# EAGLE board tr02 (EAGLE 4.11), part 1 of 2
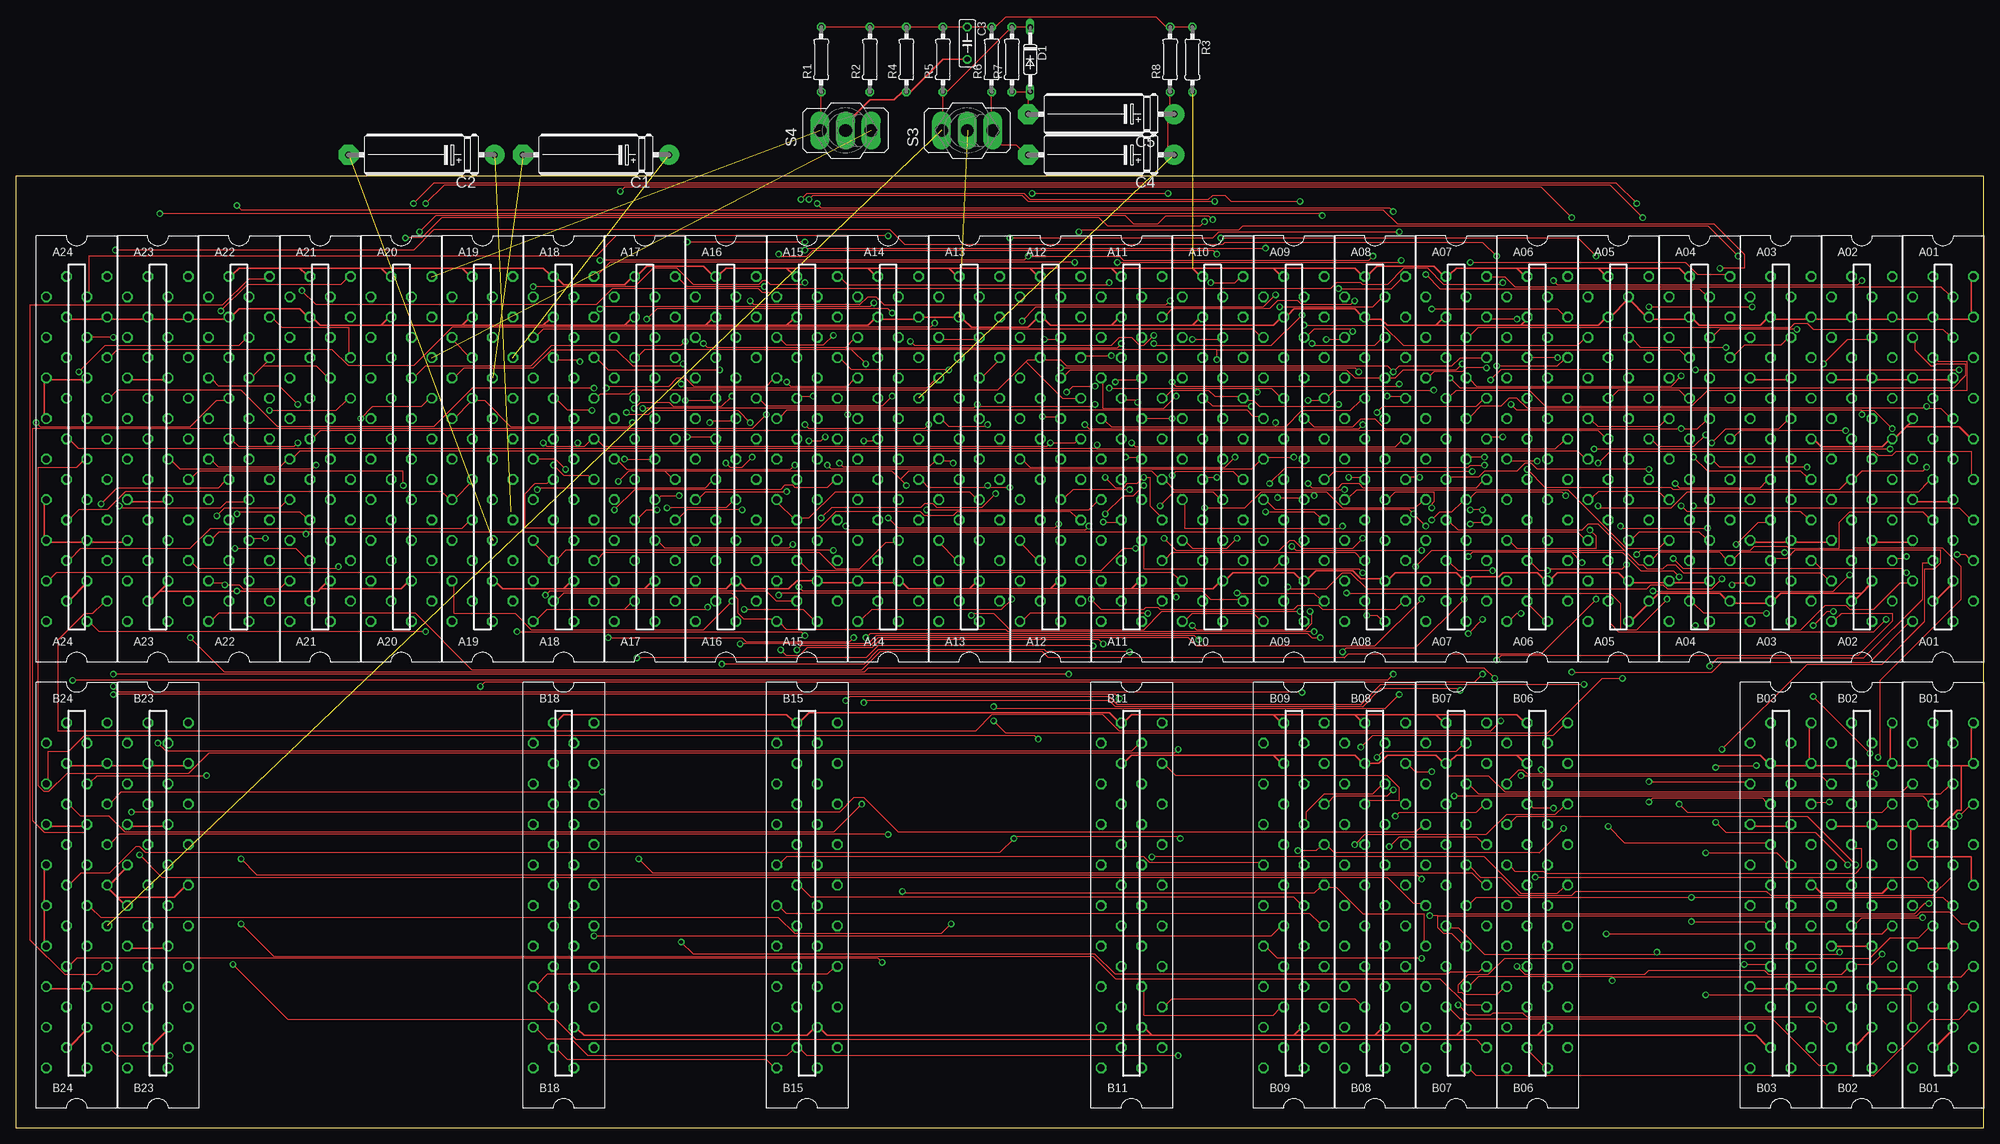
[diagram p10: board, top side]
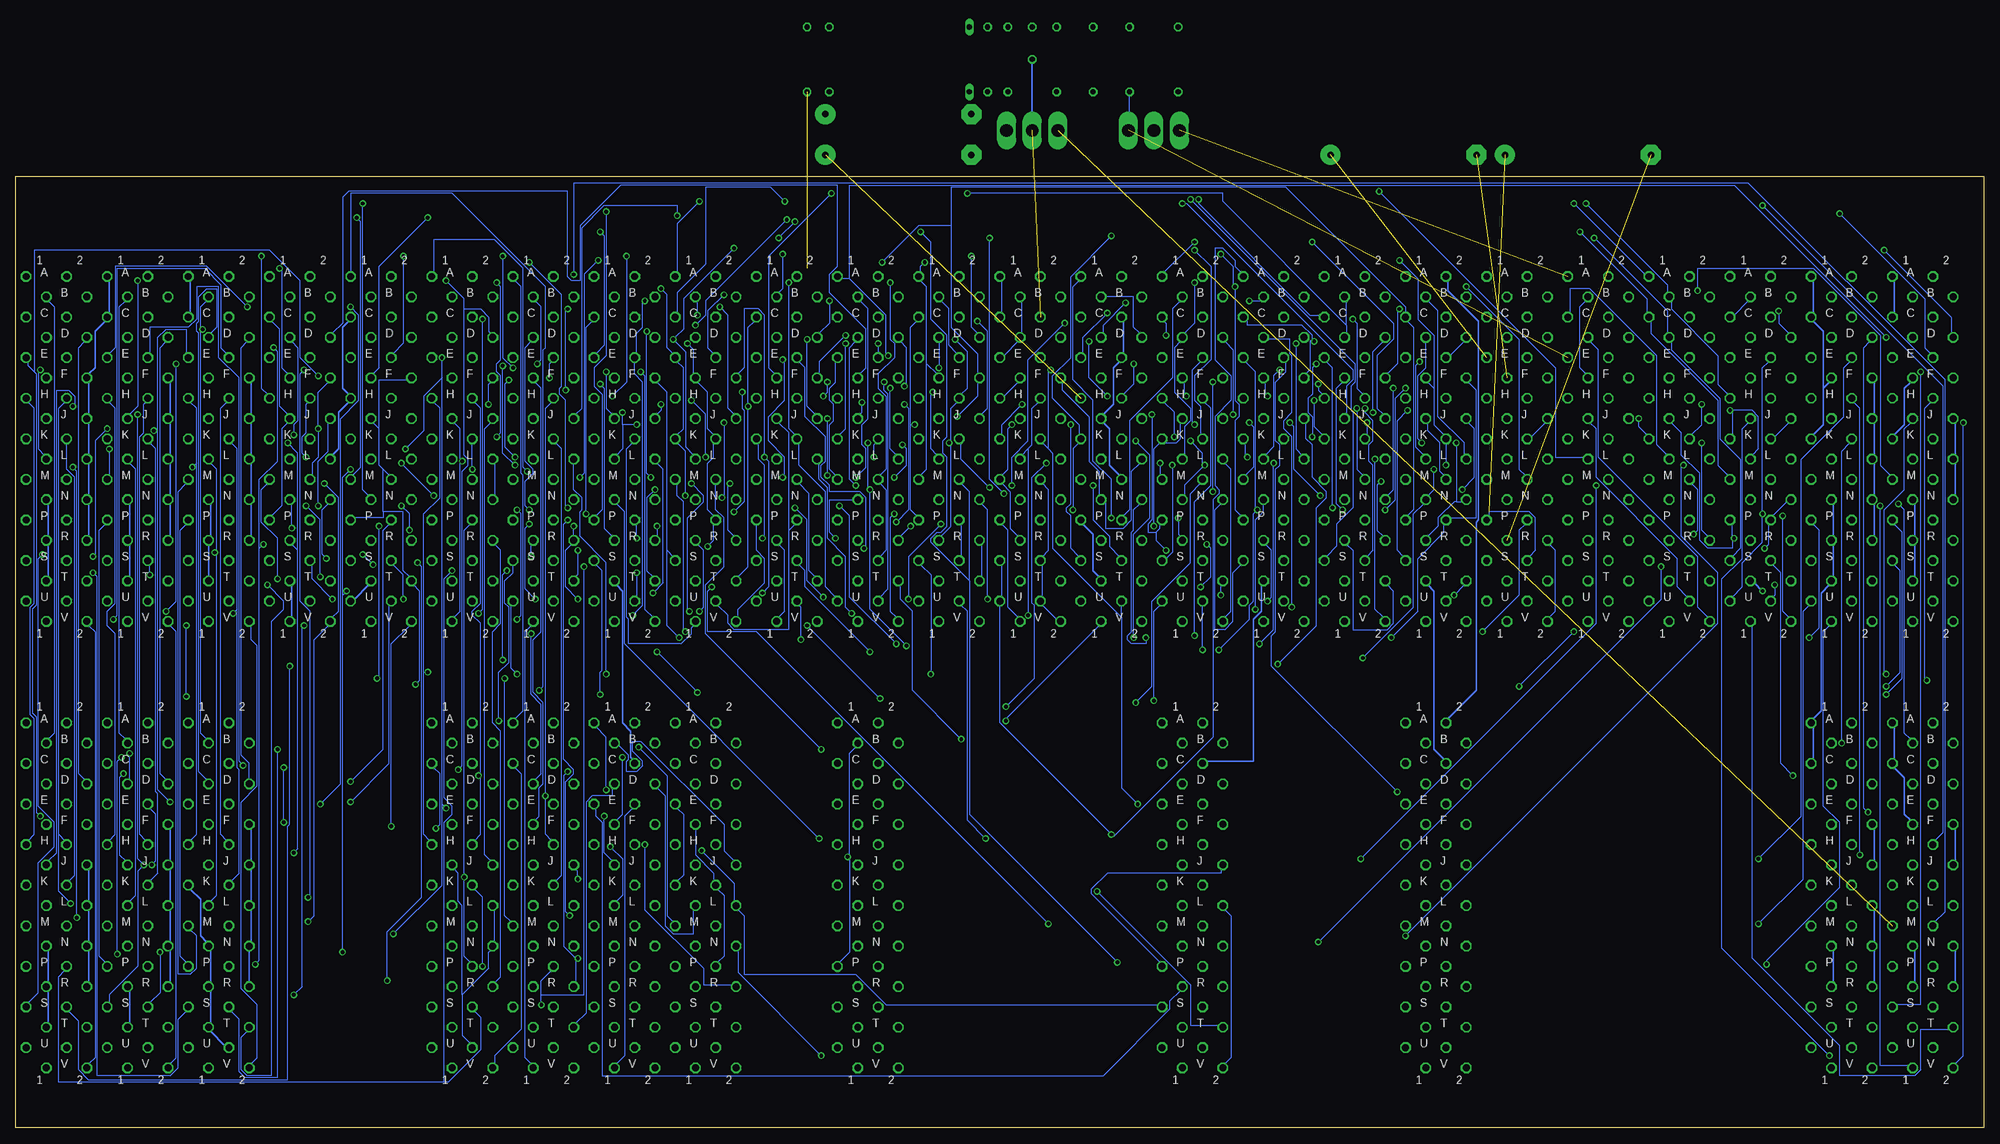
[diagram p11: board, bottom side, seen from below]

Size 307.96 x 148.9 mm. Coordinates in mm from the lower left corner, seen from the top.
Outline: 307.96,148.9 0,148.9 0,0 307.96,0 307.96,148.9
Copper layers (1*16): Top 0.035mm / dielectric 1.5mm / Bottom 0.035mm
Design rules "8mils": minimum track width 5mil, minimum drill 24mil, track to track 5mil, track to pad 8mil, pad to pad 8mil, via to via 5mil, smd to smd 8mil, copper to edge 40mil, drill to drill 10mil, minimum pad ring 10mil, minimum via ring 8mil, stop-mask expansion 0mil, vias tented up to drill 0mil, thermal gap 10mil
Net classes: 1 supply: width 0.203 mm

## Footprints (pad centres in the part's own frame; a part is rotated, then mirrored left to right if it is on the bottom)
H807 = drill 1.092 octagon: A1 4.763,28.575; A2 -1.587,28.575; B1 1.587,25.4; B2 -4.763,25.4; C1 4.763,22.225; C2 -1.587,22.225; D1 1.587,19.05; D2 -4.763,19.05; E1 4.763,15.875; E2 -1.587,15.875; F1 1.587,12.7; F2 -4.763,12.7; H1 4.763,9.525; H2 -1.587,9.525; J1 1.587,6.35; J2 -4.763,6.35; K1 4.763,3.175; K2 -1.587,3.175; L1 1.587,0; L2 -4.763,0; M1 4.763,-3.175; M2 -1.587,-3.175; N1 1.587,-6.35; N2 -4.763,-6.35; P1 4.763,-9.525; P2 -1.587,-9.525; R1 1.587,-12.7; R2 -4.763,-12.7; S1 4.763,-15.875; S2 -1.587,-15.875; T1 1.587,-19.05; T2 -4.763,-19.05; U1 4.763,-22.225; U2 -1.587,-22.225; V1 1.587,-25.4; V2 -4.763,-25.4
E22-6 = drill 1.016 pad 3.15 round: + -11.43,0 | drill 1.016 pad 3.15 octagon: - 11.43,0
C050-025X075 = drill 0.813 octagon: 1 -2.54,0; 2 2.54,0
DO35-10 = drill 0.813 long: A 5.08,0; C -5.08,0
0207/10 = drill 0.813 octagon: 1 -5.08,0; 2 5.08,0
320-916 = drill 2.007 long: 1 0,4.013; 2 0,0; 3 0,-4.013

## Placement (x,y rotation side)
A01  M903  [H807]  301.61,104.61 0 top
A02  M903  [H807]  288.91,104.61 0 top
A03  M903  [H807]  276.21,104.61 0 top
A04  [H807]  263.51,104.61 0 top
A05  [H807]  250.81,104.61 0 top
A06  [H807]  238.11,104.61 0 top
A07  M101  [H807]  225.41,104.61 0 top
A08  M111  [H807]  212.71,104.61 0 top
A09  M115  [H807]  200.01,104.61 0 top
A10  M206X  [H807]  187.31,104.61 0 top
A11  [H807]  174.61,104.61 0 top
A12  [H807]  161.91,104.61 0 top
A13  M307  [H807]  149.21,104.61 0 top
A14  M206X  [H807]  136.51,104.61 0 top
A15  M115  [H807]  123.81,104.61 0 top
A16  M111  [H807]  111.11,104.61 0 top
A17  M113  [H807]  98.41,104.61 0 top
A18  M117  [H807]  85.71,104.61 0 top
A19  [H807]  73.01,104.61 0 top
A20  M162  [H807]  60.31,104.61 0 top
A21  M162  [H807]  47.61,104.61 0 top
A22  [H807]  34.91,104.61 0 top
A23  G784  [H807]  22.21,104.61 0 top
A24  G784  [H807]  9.51,104.61 0 top
B01  M903  [H807]  301.61,34.76 0 top
B02  M903  [H807]  288.91,34.76 0 top
B03  M903  [H807]  276.21,34.76 0 top
B06  [H807]  238.11,34.76 0 top
B07  M101  [H807]  225.41,34.76 0 top
B08  M111  [H807]  212.71,34.76 0 top
B09  M115  [H807]  200.01,34.76 0 top
B11  [H807]  174.61,34.76 0 top
B15  M115  [H807]  123.81,34.76 0 top
B18  [H807]  85.71,34.76 0 top
B23  G784  [H807]  22.21,34.76 0 top
B24  G784  [H807]  9.51,34.76 0 top
C1  1uf  [E22-6]  not placed on the board
C2  1uf  [E22-6]  not placed on the board
C3  .01uf  [C050-025X075]  148.89,169.7 270 top  (outside the outline)
C4  1uf  [E22-6]  169.85,152.24 180 top  (outside the outline)
C5  1uf  [E22-6]  169.85,158.59 180 top  (outside the outline)
D1  D664  [DO35-10]  158.74,167.16 270 top  (outside the outline)
R1  10K  [0207/10]  126.03,167.16 90 top  (outside the outline)
R2  10K  [0207/10]  133.65,167.16 90 top  (outside the outline)
R3  330  [0207/10]  184.14,167.16 270 top  (outside the outline)
R4  750  [0207/10]  139.37,167.16 90 top  (outside the outline)
R5  10K  [0207/10]  145.08,167.16 90 top  (outside the outline)
R6  10K  [0207/10]  152.7,167.16 90 top  (outside the outline)
R7  10K  [0207/10]  155.88,167.16 90 top  (outside the outline)
R8  10K  [0207/10]  180.64,167.16 90 top  (outside the outline)
S3  [320-916]  148.89,156.05 90 top  (outside the outline)
S4  [320-916]  129.84,156.05 90 top  (outside the outline)

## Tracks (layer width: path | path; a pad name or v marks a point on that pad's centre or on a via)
0AC00H  (via drill 0.61)
  Top 0.127: v84.12,103.66 85.71,102.07 89.52,102.07 89.84,101.75 A18.M1 | v91.42,135.72 157.78,135.72 v158.42,136.36 158.74,136.36 172.71,136.36 173.34,135.72 211.76,135.72 v212.39,136.36 | v214.62,114.45 216.84,114.45 A08.H1
  Bottom 0.127: 86.03,115.72 86.03,110.01 84.44,108.42 A18.K2 84.12,107.15 v84.12,103.66 | 86.03,115.72 86.98,116.67 A18.F1 | v158.42,136.36 158.42,125.25 157.47,124.29 A12.D2 | v91.42,135.72 88.57,132.87 88.57,126.52 86.03,123.98 86.03,115.72 | v214.62,114.45 212.39,116.67 v212.39,136.36
0AC00L  (via drill 0.61)
  Top 0.127: A12.F1 164.13,117.63 165.09,118.58 208.27,118.58 209.54,117.31 213.66,117.31 A08.F1 214.93,117.31 215.89,117.31 217.16,118.58 225.41,118.58 v226.36,119.53 | v165.72,135.41 93.01,135.41 91.11,133.5 A18.A1
  Bottom 0.127: 165.4,119.53 163.82,117.94 A12.F1 | 165.4,119.53 165.4,131.6 166.36,132.55 A12.A1 166.36,133.82 166.36,134.77 v165.72,135.41 | 165.4,119.53 165.4,103.02 166.36,102.07 A12.M1 | v226.36,119.53 225.73,120.17 225.73,128.42 226.68,129.38 A07.B1
0AC01H  (via drill 0.61)
  Top 0.127: v86.03,103.02 84.44,104.61 81.58,104.61 A18.L2 | v174.29,99.85 165.4,99.85 164.13,98.58 A12.N1 | v174.61,107.15 175.25,106.52 215.89,106.52 216.84,107.47 A08.K1 | v97.14,73.49 133.02,73.49 134.92,75.4 v168.58,75.4
  Bottom 0.127: v86.03,103.02 86.03,99.85 86.98,98.89 A18.N1 87.61,97.62 89.2,96.04 89.2,81.43 v97.14,73.49 | A18.B1 86.98,129.38 85.39,127.79 85.39,111.28 81.27,107.15 81.27,105.24 A18.L2 | v174.61,107.15 174.61,100.16 v174.29,99.85 174.29,99.53 174.29,81.11 v168.58,75.4
0AC01L  (via drill 0.61)
  Top 0.127: A07.E1 229.54,120.48 226.05,120.48 224.78,119.21 216.52,119.21 v215.57,118.26 215.25,118.58 214.62,119.21 164.45,119.21 163.5,120.17 160.96,120.17 A12.E2 159.69,120.17 158.42,120.17 158.1,119.85 | 158.1,119.85 153.66,115.4 96.5,115.4 95.87,114.77 91.42,114.77 91.11,114.45 A18.H1 | 158.1,119.85 163.82,114.13 166.04,114.13 A12.H1
  Bottom 0.127: v215.57,118.26 215.57,112.55 214.62,111.59 A08.J1 | A12.B1 163.18,129.38 161.91,128.11 161.91,122.39 160.64,121.12 A12.E2
0AC02H  (via drill 0.61)
  Top 0.127: v219.7,101.75 218.11,101.75 A08.M1 | v216.84,135.72 216.52,135.41 v172.39,135.41 | v160.64,111.28 162.86,111.28 A12.J1
  Bottom 0.127: A18.P1 90.16,95.72 89.2,96.67 89.2,125.25 90.16,126.2 A18.C1 90.47,127.47 90.47,128.42 109.2,147.16 161.59,147.16 161.59,141.12 | v219.7,101.75 219.06,102.39 219.06,133.5 v216.84,135.72 | v172.39,135.41 166.67,141.12 161.59,141.12 | 161.59,141.12 161.59,125.25 157.47,121.12 157.47,117.94 A12.F2 157.47,116.67 157.47,114.45 v160.64,111.28
0AC02L  (via drill 0.61)
  Top 0.127: v213.03,111.91 213.98,112.86 228.59,112.86 229.54,113.82 A07.H1 | A18.M2 83.49,101.12 83.17,100.8 81.27,100.8 79.68,99.21 79.68,93.81 125.72,93.81 128.26,96.35 141.59,96.35 142.23,95.72 146.67,95.72 147.31,96.35 165.09,96.35 166.04,95.4 A12.P1 | v210.81,110.01 210.17,109.37 167.94,109.37 v167.31,110.01
  Bottom 0.127: 213.03,110.01 v213.03,111.91 | 213.03,110.01 213.03,106.2 213.98,105.24 A08.L1 | A18.M2 84.44,102.07 85.08,102.7 85.08,107.15 86.98,109.05 86.98,110.32 A18.J1 | 167.94,110.01 167.94,125.25 166.99,126.2 A12.C1 | 167.94,110.01 167.94,96.67 166.99,95.72 A12.P1 | v210.81,110.01 213.03,110.01 | 167.94,110.01 v167.31,110.01
0B01B_L  (via drill 0.61)
  Top 0.127: v220.65,133.5 222.87,131.28 263.51,131.28 264.46,130.33 A04.B1
  Bottom 0.127: v220.65,133.5 220.65,147.79 36.81,147.79 6.02,116.99 6.02,33.81 7.61,32.22 B24.M2
0BOT_FF_H  (via drill 0.61)
  Top 0.127: v155.88,82.7 154.29,81.11 133.97,81.11 132.38,79.53 A14.V2
  Bottom 0.127: v155.88,82.7 155.88,96.67 156.83,97.62 A12.N2
0BOT_L  (via drill 0.61)
  Top 0.127: v132.38,50.63 127.94,46.19 17.13,46.19 14.59,48.73 10.14,48.73 8.56,50.32 B24.E2 | v146.04,118.58 130.8,118.58 129.21,120.17 A15.E1
  Bottom 0.127: v132.38,50.63 134.92,53.18 134.92,79.84 | 134.92,79.84 134.92,81.75 A14.U2 | 146.35,106.2 145.72,105.56 145.72,90.64 134.92,79.84 | 146.35,106.2 147.31,107.15 A13.K2 | v146.04,118.58 146.35,118.26 146.35,106.2
0BOTFF_L  (via drill 0.61)
  Top 0.127: v153.02,63.65 154.93,61.75 239.7,61.75 248.27,70.32 v251.45,70.32 | v251.13,94.13 251.45,93.81 v264.78,93.81
  Bottom 0.127: v153.02,63.65 153.02,63.97 138.42,78.57 A14.V1 | v251.45,70.32 251.13,70.64 v251.13,94.13 | v264.78,93.81 264.78,97.62 A04.N1
0DATA_BUSY_L  (via drill 0.61)
  Top 0.127: v117.46,111.59 115.24,109.37 2.52,109.37 2.52,48.09 4.43,46.19 10.78,46.19 10.78,41.74 B24.J1 | v127.94,123.98 126.35,122.39 120.64,122.39 119.68,123.34 A15.D2
  Bottom 0.127: v117.46,111.59 117.46,121.75 118.73,123.02 A15.D2 | v127.94,123.98 127.94,125.88 128.26,126.2 A15.C1
0DENSITY_SEL  (1 unrouted)
  Top 0.127: D1.C 158.1,172.24 156.51,172.24 R7.2 155.56,171.92 145.72,162.08 R5.1 145.08,161.44 145.08,158.9 S3.1
0DISABLE_MANCTL_L  (via drill 0.61)
  Top 0.127: v155.56,100.16 152.07,100.16 | 152.07,100.16 142.86,100.16 141.91,101.12 A14.M1 | v143.81,125.88 143.18,125.25 68.25,125.25 62.21,119.21 52.05,119.21 49.52,121.75 15.86,121.75 14.91,120.8 A24.E1 | 152.07,100.16 v152.07,100.48
  Bottom 0.127: v155.56,100.16 160.01,104.61 160.01,107.15 A12.K2 | v143.81,125.88 149.53,120.17 149.53,107.47 152.07,104.93 v152.07,100.48
0ENABLE_L  (1 unrouted)
  Top 0.127: R8.1 180.64,161.44 180.64,159.86 C5.+ 180.33,157.31 180.33,153.5 C4.+
0EOT_L  (via drill 0.61)
  Top 0.127: v160.01,60.8 159.37,61.43 10.78,61.43 8.24,58.89 5.07,58.89 5.07,54.45 B24.D2
  Bottom 0.127: v160.01,60.8 167.62,68.41 167.62,80.8 169.53,82.7 169.53,84.92 A11.T2
0EOTFF_L  (via drill 0.61)
  Top 0.127: v172.07,116.67 172.39,116.99 175.56,116.99 A11.F1
  Bottom 0.127: v172.07,116.67 172.07,115.4 171.44,114.77 171.44,84.29 172.71,83.02 A11.U2 | A04.D2 258.43,124.29 256.84,125.88 256.84,145.57 255.89,146.52 221.6,146.52 221.6,133.19 220.97,132.55 219.7,132.55 219.7,141.12 213.35,147.47 179.37,147.47 179.37,134.77 180.64,133.5 180.64,130.65 174.93,124.93 174.93,118.9 175.88,117.94 A11.F1
0FILE_PROT_L  (via drill 0.61)
  Top 0.127: v146.35,31.9 144.77,30.32 121.91,30.32 119.36,32.86 13.32,32.86 11.73,34.44 B24.L1 | v199.06,84.61 199.38,84.29 205.09,84.29 207.63,86.83 208.9,86.83 211.44,84.29 255.26,84.29 255.89,84.92 257.8,84.92 258.43,84.29 265.42,84.29 v267,85.88
  Bottom 0.127: v146.35,31.9 192.07,77.62 199.69,77.62 199.69,83.97 v199.06,84.61 | v267,85.88 267,92.23 269.54,94.77 269.54,99.85 268.59,100.8 A04.M1
0FILEGAP_L  (via drill 0.61)
  Top 0.127: v164.77,70.95 v15.22,70.95
  Bottom 0.127: v164.77,70.95 164.77,86.51 166.36,88.1 A12.S1 | v15.22,70.95 15.54,71.27 15.54,96.67 12.37,99.85 12.37,109.37 11.41,110.32 A24.J1
0FWD_ENABLE  (via drill 0.61)
  Top 0.127: v123.49,138.58 v105.08,138.58 | v171.12,132.23 170.8,131.92 130.16,131.92 129.21,132.87 A15.A1
  Bottom 0.127: A11.S2 172.71,89.37 171.75,90.32 171.75,99.85 172.71,100.8 A11.M2 172.71,102.07 171.75,103.02 171.75,114.45 173.02,115.72 173.02,117.94 170.48,120.48 170.48,122.71 171.12,123.34 v171.12,132.23 | v105.08,138.58 92.38,125.88 92.38,123.34 94.92,120.8 94.92,112.55 93.97,111.59 A17.J2 | v123.49,138.58 128.26,133.82 A15.A1
0FWD_LD_L  (via drill 0.61)
  Top 0.127: v190.8,104.93 189.22,103.34 158.74,103.34 157.78,104.29 A12.L2 | v191.12,83.65 203.19,83.65 204.14,82.7 A09.U1
  Bottom 0.127: A09.F2 194.93,117.94 193.98,118.9 193.98,128.11 191.76,128.11 190.8,127.15 v190.8,104.93 190.49,104.61 190.17,104.29 190.17,84.61 v191.12,83.65
0GAP_H  (via drill 0.61)
  Top 0.127: v104.12,116.36 104.76,115.72 142.54,115.72 143.81,116.99 A13.F2
  Bottom 0.127: v104.12,116.36 104.12,115.4 103.49,114.77 A17.H1 | A13.F2 144.13,116.67 144.13,115.4 140,111.28 140,104.29 138.42,102.7 138.42,98.89 A14.N1 137.46,97.94 137.46,93.81 134.61,93.81 133.34,95.08 133.34,102.7 132.07,103.97 A14.L2
0GAP_L  (via drill 0.61)
  Top 0.127: v200.96,80.8 179.37,80.8 176.52,77.94 155.56,77.94 153.02,80.48 149.85,80.48 v149.53,80.16
  Bottom 0.127: 149.53,106.2 148.89,106.83 148.89,112.55 147.94,113.5 A13.H2 | 149.53,106.2 150.48,105.24 A13.L1 | v200.96,80.8 200.33,81.43 200.33,90.32 201.28,91.27 A09.R1 | 149.53,106.2 v149.53,80.16
0GAPSP_L  (via drill 0.61)
  Top 0.127: v107.62,122.71 108.25,122.07 129.84,122.07 | 129.84,122.07 131.11,123.34 A14.D2 | v173.02,122.71 172.39,122.07 129.84,122.07
  Bottom 0.127: v107.62,122.71 107.62,106.2 106.67,105.24 A16.L2 | A14.B1 137.46,130.01 133.02,130.01 133.02,125.25 132.07,124.29 A14.D2 | v173.02,122.71 173.02,121.12 A11.E2
0GIP_L  (via drill 0.61)
  Top 0.127: v135.56,25.87 134.92,26.51 9.51,26.51 8.56,25.55 B24.P2 | v269.54,136.36 264.78,141.12 192.07,141.12 191.44,140.49 166.67,140.49 v166.36,140.17
  Bottom 0.127: v135.56,25.87 158.74,49.05 158.74,85.56 | 158.74,85.56 158.74,99.53 160.01,100.8 A12.M2 | v269.54,136.36 269.54,115.72 268.59,114.77 A04.H1 | v166.36,140.17 164.77,138.58 164.77,126.52 162.23,123.98 162.23,108.1 162.86,107.47 162.86,105.56 162.23,104.93 162.23,94.13 163.18,93.18 163.82,93.18 164.77,92.23 164.77,91.59 158.74,85.56
0INITA_L  (via drill 0.61)
  Top 0.127: v132.7,107.47 134.29,107.47 A14.K2 | v133.02,76.67 133.65,77.3 202.23,77.3 202.87,76.67 v204.14,76.67
  Bottom 0.127: 206.04,90.32 205.09,89.37 A09.S1 | 206.04,90.32 206.04,115.09 207.63,116.67 A08.F2 | v132.7,107.47 130.48,105.24 130.48,95.4 133.02,92.86 v133.02,76.67 | v204.14,76.67 206.04,78.57 206.04,90.32
0INITB_L  (via drill 0.61)
  Top 0.127: v136.51,95.4 138.1,93.81 162.55,93.81 v163.18,94.45 | v168.26,82.7 169.85,81.11 176.52,81.11 176.83,81.43 178.74,81.43 179.06,81.11 200.01,81.11 200.65,81.75 203.82,81.75 204.46,81.11 215.89,81.11 216.84,82.07 A08.U1
  Bottom 0.127: v136.51,95.4 136.51,101.43 139.37,104.29 139.37,113.82 142.54,116.99 142.54,131.6 141.59,132.55 A14.A1 | v163.18,94.45 168.26,89.37 v168.26,82.7
0IOT01L  (via drill 0.61)
  Top 0.127: v113.97,81.11 123.17,81.11 124.76,79.53 A15.V1 | v101.9,96.99 111.11,96.99 112.06,97.94 A16.N1
  Bottom 0.127: v113.97,81.11 113.97,95.08 112.7,96.35 112.7,97.62 A16.N1 | v101.9,96.99 101.9,118.9 102.86,119.85 A17.E1
0IOT02L  (via drill 0.61)
  Top 0.127: A09.J1 202.23,110.64 203.19,109.69 209.22,109.69 210.49,110.96 212.71,110.96 214.3,109.37 v260.65,109.37 263.19,109.37 264.46,110.64 A04.J1
  Bottom 0.127: A04.F2 259.06,116.67 260.65,115.09 v260.65,109.37 260.65,104.93 261.61,103.97 261.61,102.07 A04.M2 | A04.P1 267.96,95.72 266.37,97.31 266.37,109.37 265.42,110.32 A04.J1 265.42,111.59 266.69,112.86 266.69,124.93 267.96,126.2 A04.C1
0IOT03_1L  (via drill 0.61)
  Top 0.127: 197.15,109.69 198.74,109.69 201.28,112.23 208.9,112.23 210.49,113.82 A08.H2 | 197.15,109.69 171.44,109.69 170.48,110.64 A11.J2 | v197.47,98.58 200.96,98.58 A09.N1 | 197.15,109.69 v197.15,110.32
  Bottom 0.127: v197.47,98.58 197.15,98.89 v197.15,110.32
0IOT04L  (via drill 0.61)
  Top 0.127: 196.84,87.46 176.52,87.46 176.52,91.27 A11.R1 | 196.84,87.46 197.79,88.42 A09.S2 | v210.81,86.83 210.17,87.46 196.84,87.46
  Bottom 0.127: v210.81,86.83 210.81,83.02 A08.U2
0IOT05_1L  (via drill 0.61)
  Top 0.127: 95.23,81.11 83.17,81.11 81.58,79.53 A18.V2 | 95.23,81.11 96.19,82.07 A17.U2 | v108.25,81.43 107.94,81.11 95.23,81.11
  Bottom 0.127: v108.25,81.43 108.25,108.1 109.52,109.37 109.52,110.64 108.25,111.91 108.25,120.8 108.57,121.12 108.57,123.34 112.06,123.34 A16.D1
0IOT06_2L  (via drill 0.61)
  Top 0.127: v181.91,59.21 181.28,58.57 30.15,58.57 26.97,55.4 7.92,55.4 5.07,52.54 4.43,52.54 3.48,53.49 3.48,103.34 9.51,103.34 10.46,104.29 A24.L1
  Bottom 0.127: v181.91,59.21 200.01,77.3 200.01,84.92 197.15,87.78 197.15,95.4 198.42,96.67 198.42,100.8 A09.M2
0IOT07_1L  (via drill 0.61)
  Top 0.127: v132.7,66.51 133.02,66.83 171.12,66.83 172.07,65.88 210.81,65.88 213.66,68.73 225.73,68.73 v226.05,68.41
  Bottom 0.127: v132.7,66.51 130.16,69.05 130.16,82.38 124.13,88.42 124.13,99.21 122.54,100.8 A15.M2 | v226.05,68.41 225.41,69.05 225.41,121.75 225.09,122.07 225.09,131.6 239.7,146.2 255.57,146.2 255.57,133.82 A05.A1
0IOT07_2L  (via drill 0.61)
  Top 0.127: v129.84,66.83 130.48,67.46 171.12,67.46 172.39,66.19 210.49,66.19 213.66,69.37 v245.41,69.37
  Bottom 0.127: 250.49,103.02 251.13,103.66 251.13,109.37 | 250.49,103.02 249.54,102.07 A05.M2 | 251.13,109.37 252.08,110.32 A05.J1 | 251.13,109.37 251.13,116.99 246.68,116.99 A05.F2 | 250.49,96.35 250.49,103.02 | 250.49,96.35 250.49,95.4 254.94,95.4 A05.P1 | v129.84,66.83 129.84,80.8 128.89,81.75 A15.U1 | v245.41,69.37 244.78,70 244.78,83.97 245.73,84.92 A05.T2 246.37,86.19 247.32,87.15 247.32,96.35 250.49,96.35
0IRG_H  (via drill 0.61)
  Top 0.127: v181.6,114.45 179.69,112.55 170.17,112.55 170.17,116.67 A11.F2 | v180.96,116.67 181.6,116.04 216.2,116.04 v216.52,116.36
  Bottom 0.127: v181.6,114.45 180.96,115.09 v180.96,116.67 | v216.52,116.36 215.89,115.72 215.89,93.81 214.62,92.54 A08.R1
0IRG_L  (via drill 0.61)
  Top 0.127: v128.89,103.97 129.53,103.34 142.86,103.34 143.81,104.29 A13.L2 145.08,104.29 146.35,104.29 v146.67,103.97 | v90.47,115.72 71.42,115.72 65.39,109.69 40.94,109.69 35.23,115.4 15.86,115.4 14.91,114.45 A24.H1 | v93.65,96.67 96.82,99.85 119.68,99.85 120.32,100.48 121.59,100.48 121.91,100.16 126.98,100.16 127.94,101.12 A15.M1 | v216.52,67.78 214.3,65.56 153.34,65.56 v153.02,65.88
  Bottom 0.127: v128.89,103.97 128.89,102.07 A15.M1 | v90.47,115.72 92.06,114.13 92.06,98.26 v93.65,96.67 | v216.52,67.78 216.52,71.27 216.2,71.59 216.2,87.15 217.16,88.1 A08.S1 | v153.02,65.88 148.58,70.32 148.58,81.75 148.89,82.07 148.89,101.75 v146.67,103.97
0LD_FWD_L  (via drill 0.61)
  Top 0.127: v142.54,96.67 167.94,96.67 169.21,97.94 A11.N2 | v136.51,139.53 93.97,139.53 90.79,136.36 11.41,136.36 11.41,130.65 A24.B1
  Bottom 0.127: v142.54,96.67 142.54,106.2 141.59,107.15 A14.K1 141.59,108.42 141.59,110.01 145.72,114.13 145.72,117.63 142.86,120.48 142.86,133.19 v136.51,139.53
0LPE_L  (via drill 0.61)
  Top 0.127: v94.6,146.52 95.23,147.16 238.75,147.16 v243.51,142.39
  Bottom 0.127: v94.6,146.52 66.98,118.9 66.98,104.93 62.53,104.93 A20.L1 | v243.51,142.39 251.13,134.77 251.13,118.9 252.08,117.94 A05.F1
0MB09H  (via drill 0.61)
  Top 0.127: A18.R2 81.27,91.27 83.49,89.05 A18.S2 84.76,89.05 86.03,90.32 v127.94,90.32 | 130.16,112.23 192.71,112.23 193.66,111.28 194.61,111.28 A09.J2 | 130.16,112.23 120.64,112.23 119.68,111.28 A15.J2 | 130.16,112.23 v130.16,111.59 | v197.79,128.42 212.39,128.42 213.66,129.69 A08.B1
  Bottom 0.127: 129.53,93.18 128.89,93.81 128.89,94.45 A15.P1 | 129.53,93.18 130.8,93.18 130.8,94.45 130.16,95.08 v130.16,111.59 | v197.79,128.42 196.52,127.15 196.52,112.55 195.57,111.59 A09.J2 | v127.94,90.32 129.53,91.91 129.53,93.18
0MB09L  (via drill 0.61)
  Top 0.127: v207,131.28 215.25,131.28 216.84,132.87 A08.A1 | v119.36,83.34 119.68,83.65 180.96,83.65 v181.6,83.02 | v186.04,96.99 192.39,96.99 194.93,99.53 203.19,99.53 | 203.19,99.53 205.09,99.53 207.63,96.99 219.06,96.99 220.01,97.94 A07.N2 | 203.19,99.53 v203.19,98.89
  Bottom 0.127: v207,131.28 206.04,130.33 206.04,122.07 205.09,121.12 A09.E1 204.46,119.85 203.5,118.9 203.5,109.37 204.46,108.42 A09.K1 204.46,107.15 203.19,105.88 v203.19,98.89 | v119.36,83.34 119.36,84.92 A15.T2 | v181.6,83.02 184.14,85.56 184.14,95.08 v186.04,96.99
0MB10H  (via drill 0.61)
  Top 0.127: v205.09,123.34 207.31,123.34 A08.D2 | v123.49,137.31 123.81,137.63 v195.57,137.63
  Bottom 0.127: A09.L1 201.92,105.24 203.19,106.52 203.19,121.44 v205.09,123.34 204.77,123.66 203.5,124.93 203.5,129.69 v195.57,137.63 | v123.49,137.31 120.95,134.77 120.95,120.17 123.49,117.63 123.49,113.82 122.54,112.86 122.54,108.42 A15.K2
0MB10L  (via drill 0.61)
  Top 0.127: v82.85,83.34 83.49,83.97 117.46,83.97 119.05,82.38 121.59,82.38 A15.U2 | v220.65,94.13 v218.74,96.04 218.11,96.67 197.15,96.67 195.88,97.94 A09.N2 | v122.22,74.77 122.86,75.4 133.65,75.4 134.92,76.67 183.5,76.67 184.77,75.4 212.71,75.4 v220.01,82.7
  Bottom 0.127: v82.85,83.34 81.27,84.92 A18.T2 | v220.65,94.13 220.65,92.54 A07.R2 220.97,91.27 221.92,90.32 221.92,84.61 v220.01,82.7 | v218.74,96.04 218.74,125.25 217.79,126.2 A08.C1 | v122.22,74.77 122.22,81.75 A15.U2
0MB11H  (via drill 0.61)
  Top 0.127: v126.03,95.4 127.62,96.99 141.59,96.99 142.23,97.62 143.5,97.62 144.13,96.99 151.12,96.99 v153.34,99.21 | v155.56,139.22 187.31,139.22 188.26,140.17 v216.52,140.17
  Bottom 0.127: v126.03,95.4 126.03,92.86 125.72,92.54 A15.R1 | v153.34,99.21 155.56,101.43 v155.56,139.22 | v216.52,140.17 215.89,139.53 215.89,122.39 217.16,121.12 A08.E1
0MB11L  (via drill 0.61)
  Top 0.127: v220.01,90.32 200.33,90.32 v199.69,90.96 | v202.87,122.71 203.19,122.39 212.71,122.39 213.66,123.34 A08.D1
  Bottom 0.127: v220.01,90.32 220.01,86.51 220.33,86.19 A07.T2 | v199.69,90.96 198.74,91.91 198.74,94.45 A09.P2 198.74,95.72 199.69,96.67 199.69,103.97 198.74,104.93 198.74,107.15 A09.K2 198.74,108.42 199.69,109.37 199.69,115.09 201.28,116.67 A09.F1 201.92,117.94 201.92,121.75 v202.87,122.71
0MYOP1  (via drill 0.61)
  Top 0.127: A18.U2 84.76,82.7 85.71,83.65 112.06,83.65 113.02,82.7 113.02,80.48 113.97,79.53 118.41,79.53 A15.V2 119.68,78.89 120.64,77.94 154.93,77.94 155.24,77.62 v203.19,77.62 | v227.95,102.7 206.36,102.7 205.41,101.75 A09.M1
  Bottom 0.127: A15.V2 118.73,79.84 117.78,80.8 117.78,103.02 118.73,103.97 A15.L2 | v227.95,102.7 228.59,103.34 228.59,134.46 233.03,138.9 242.56,138.9 242.56,133.82 A06.A1 | v203.19,77.62 203.5,77.94 203.5,97.94 204.46,98.89 204.46,100.8 A09.M1
0MYOP2  (via drill 0.61)
  Top 0.127: v126.98,103.66 127.62,103.02 193.34,103.02 194.61,104.29 A09.L2 195.88,104.93 v200.01,104.93 | v202.23,113.82 204.14,113.82 A09.H1 205.41,114.45 206.36,115.4 v221.92,115.4 | v221.6,128.11 241.29,128.11 242.24,127.15 A06.C1
  Bottom 0.127: v126.98,103.66 126.98,90 127.94,89.05 A15.S1 | v202.23,113.82 200.01,111.59 v200.01,104.93 | v221.6,128.11 221.92,127.79 v221.92,115.4
0MYOP4  (via drill 0.61)
  Top 0.127: v196.2,100.8 198.74,103.34 227.32,103.34 227.63,103.66 v229.86,103.66 | v231.76,119.21 241.29,119.21 242.24,120.17 A06.E1
  Bottom 0.127: v196.2,100.8 196.52,100.48 196.52,93.5 195.57,92.54 A09.R2 | v229.86,103.66 231.76,105.56 v231.76,119.21
0R_RESET_L  (via drill 0.61)
  Top 0.127: A11.P1 179.06,95.72 177.47,97.31 177.47,101.75 v176.52,101.75 176.2,101.43 175.56,100.8 173.98,100.8 173.34,100.16 172.07,100.16 v170.48,101.75 | 169.21,106.2 240.97,106.2 242.24,107.47 A06.K1 | 169.21,106.2 9.83,106.2 8.56,107.47 A24.K2 | v169.21,106.83 169.21,106.2
  Bottom 0.127: v176.52,101.75 174.93,103.34 174.93,106.2 175.56,106.83 175.56,110.01 174.61,110.96 174.61,128.11 175.88,129.38 A11.B1 | v170.48,101.75 168.58,103.66 168.58,106.2 v169.21,106.83
0RD00H
  Top 0.127: A21.E1 52.05,121.12 52.05,125.25 41.58,125.25 40.31,126.52 A22.C1
  Bottom 0.127: A22.B1 36.81,129.38 39.04,127.15 A22.C1
0RD00L  (via drill 0.61)
  Top 0.127: v254.62,142.39 249.54,147.47 66.98,147.47 v64.12,144.62 | v32.05,127.79 36.18,131.92 50.78,131.92 51.74,132.87 A21.A1
  Bottom 0.127: v254.62,142.39 253.99,141.76 253.99,103.34 255.26,102.07 A05.M1 | v64.12,144.62 53.01,133.5 A21.A1 | v32.05,127.79 32.05,125.88 30.46,124.29 A22.D2
0RD01H
  Top 0.127: 38.72,119.21 39.35,119.85 A22.E1 | 38.72,119.21 37.13,117.63 A22.F1 | 38.72,119.21 46.98,119.21 48.56,117.63 A21.F1
0RD01L  (via drill 0.61)
  Top 0.127: v253.67,144.62 250.49,147.79 65.39,147.79 v62.21,144.62
  Bottom 0.127: v253.67,144.62 253.67,99.85 252.72,98.89 A05.N1 | v62.21,144.62 49.52,131.92 49.52,130.65 A21.B1 48.88,129.38 48.88,128.11 41.58,120.8 41.58,116.36 39.99,114.77 A22.H1
0RD02H  (via drill 0.61)
  Top 0.127: v39.67,112.23 50.15,112.23 51.74,113.82 A21.H1
  Bottom 0.127: 39.35,112.23 36.18,112.23 35.23,111.28 35.23,106.2 36.18,105.24 A22.L1 | 39.35,112.23 39.35,108.42 A22.K1 | 39.35,112.23 v39.67,112.23
0RD02L  (via drill 0.61)
  Top 0.127: v201.6,125.56 213.98,125.56 217.16,122.39 244.46,122.39 245.41,123.34 A05.D2 | v187.31,142.08 186.68,142.71 180.01,142.71 178.74,141.44 174.93,141.44 173.66,142.71 65.71,142.71 v63.17,140.17
  Bottom 0.127: A22.M1 39.99,102.07 41.58,103.66 41.58,113.82 52.05,124.29 52.05,126.2 A21.C1 52.69,127.47 52.69,129.69 v63.17,140.17 | v201.6,125.56 200.01,127.15 200.01,129.38 v187.31,142.08
0RD03H  (via drill 0.61)
  Top 0.127: v39.04,92.23 37.13,92.23 A22.R1
  Bottom 0.127: A22.P1 39.35,94.45 39.35,92.54 v39.04,92.23 39.35,91.91 39.35,90.64 43.16,90.64 44.44,91.91 44.44,102.39 47.29,105.24 47.29,108.74 48.88,110.32 A21.J1
0RD03L  (via drill 0.61)
  Top 0.127: v247.32,136.36 244.46,139.22 v188.58,139.22 | v186.04,141.76 185.41,141.12 170.8,141.12 169.53,142.39 66.66,142.39 63.48,139.22 v60.95,139.22
  Bottom 0.127: A22.S1 39.35,89.37 38.09,90.64 38.09,104.61 41.26,107.78 41.26,114.13 48.88,121.75 48.88,123.02 A21.D1 49.52,124.29 49.52,127.79 v60.95,139.22 | v247.32,136.36 247.32,122.71 248.91,121.12 A05.E2 | v186.04,141.76 v188.58,139.22
0RD04H  (via drill 0.61)
  Top 0.127: v34.59,96.04 34.91,96.35 44.44,96.35 45.39,95.4 A21.P2
  Bottom 0.127: A22.U1 39.35,83.02 37.77,84.61 37.77,88.42 34.59,91.59 v34.59,96.04 34.59,118.9 33.64,119.85 A22.E2
0RD04L  (via drill 0.61)
  Top 0.127: v44.12,113.18 41.26,116.04 31.73,116.04 30.78,116.99 A22.F2 | A05.K2 248.59,108.1 247.64,109.05 47.61,109.05 46.66,108.1 A21.K2
  Bottom 0.127: v44.12,113.18 44.12,110.01 45.7,108.42 A21.K2
0RD05H  (via drill 0.61)
  Top 0.127: v44.12,107.15 43.48,106.52 34.91,106.52 33.96,107.47 A22.K2
  Bottom 0.127: v44.12,107.15 44.12,93.5 43.16,92.54 A21.R2 | A22.J2 30.46,110.32 32.69,108.1 A22.K2
0RD05L
  Top 0.127: A22.L2 30.78,104.29 31.73,103.34 41.26,103.34 42.21,104.29 A21.L2 43.48,104.93 44.44,105.88 244.46,105.88 245.41,104.93 A05.L2
0RD06H  (via drill 0.61)
  Top 0.127: v34.27,90.64 43.8,90.64 45.39,89.05 A21.S2
  Bottom 0.127: A22.N2 30.78,97.94 33.01,95.72 A22.P2 33.64,94.45 33.64,91.27 v34.27,90.64
0RD06L  (via drill 0.61)
  Top 0.127: A22.R2 30.78,92.23 31.73,93.18 45.07,93.18 v45.39,92.86 45.7,93.18 244.46,93.18 245.41,92.23 A05.R2
  Bottom 0.127: v45.39,92.86 44.75,93.5 44.75,99.85 45.7,100.8 A21.M2
0RD07H  (via drill 0.61)
  Top 0.127: A22.T2 30.78,85.24 32.37,85.24 v32.69,84.92 33.01,84.92 34.91,84.92 35.55,84.29 41.26,84.29 42.21,85.24 A21.T2
  Bottom 0.127: v32.69,84.92 32.69,83.34 33.01,83.02 A22.U2
0RD07L  (via drill 0.61)
  Top 0.127: v31.42,95.72 32.69,96.99 41.26,96.99 42.21,97.94 A21.N2 | v247.32,82.7 238.75,74.13 208.58,74.13 207.95,73.49 161.59,73.49 160.64,74.45 135.24,74.45 132.38,71.59 71.42,71.59 62.53,80.48 31.73,80.48 30.78,79.53 A22.V2
  Bottom 0.127: v31.42,95.72 31.42,80.8 30.46,79.84 A22.V2 | v247.32,82.7 247.32,86.51 248.91,88.1 A05.S2
0RD_DATA00L
  Top 0.127: B24.P1 13.64,24.92 12.68,23.96 7.61,23.96 2.21,29.36 2.21,128.74 32.37,128.74 36.5,132.87 39.04,132.87 A22.A1
0RD_DATA01L  (via drill 0.61)
  Top 0.127: v9.83,118.26 13.96,122.39 34.91,122.39 35.86,123.34 A22.D1
  Bottom 0.127: v9.83,118.26 9.83,19.2 13.64,19.2 B24.S1
0RD_DATA02L  (via drill 0.61)
  Top 0.127: v24.11,11.27 15.86,11.27 14.91,12.22 B24.U1
  Bottom 0.127: v24.11,11.27 40.94,28.09 40.94,85.88 37.77,89.05 37.77,109.37 36.81,110.32 A22.J1
0RD_DATA03L  (via drill 0.61)
  Top 0.127: v16.18,97.31 16.5,96.99 32.05,96.99 33.01,97.94 35.86,97.94 A22.N1
  Bottom 0.127: v16.18,97.31 16.18,9.68 11.73,9.68 B24.V1
0RD_DATA04L
  Bottom 0.127: B24.T2 5.38,15.39 9.83,15.39 9.83,9.04 10.78,8.09 22.53,8.09 22.53,12.85 36.18,26.51 36.18,78.57 A22.V1
0RD_DATA05L  (via drill 0.61)
  Top 0.127: v3.16,110.32 3.79,109.69 27.29,109.69 31.42,113.82 32.69,113.82 A22.H2
  Bottom 0.127: v3.16,110.32 3.16,11.27 4.43,10 B24.V2
0RD_DATA06L  (via drill 0.61)
  Top 0.127: v13.32,97.62 15.86,100.16 31.73,100.16 32.69,101.12 A22.M2
  Bottom 0.127: v13.32,97.62 12.37,96.67 12.37,61.75 11.41,60.8 B24.B1
0RD_DATA07L  (via drill 0.61)
  Top 0.127: v29.83,55.08 12.68,55.08 11.73,54.13 B24.D1
  Bottom 0.127: v29.83,55.08 31.73,56.98 31.73,86.83 33.01,88.1 A22.S2
0RD_ENABLE_L  (via drill 0.61)
  Top 0.127: v175.25,90.64 173.34,90.64 169.85,87.15 124.13,87.15 122.86,88.42 A15.S2
  Bottom 0.127: v175.25,90.64 174.93,90.96 174.93,98.58 175.88,99.53 180.64,99.53 180.64,100.48 181.91,101.75 181.91,103.66 181.28,104.29 181.28,108.1 184.45,111.28 184.45,118.9 185.41,119.85 A10.E2
0RD_FWD_L  (via drill 0.61)
  Top 0.127: v131.11,76.67 130.48,76.03 114.28,76.03 113.65,76.67 v92.69,76.67
  Bottom 0.127: A18.F2 80.63,116.67 79.36,115.4 79.36,95.4 83.49,95.4 A18.P2 84.44,94.45 84.44,93.18 88.57,89.05 88.57,80.8 v92.69,76.67 | v131.11,76.67 131.11,75.72 133.34,75.72 133.97,76.35 133.97,76.99 133.34,77.62 133.34,93.18 133.02,93.5 133.02,96.67 132.07,97.62 A14.N2
0RD_LD_L  (via drill 0.61)
  Top 0.127: v88.25,119.85 87.93,120.17 84.76,120.17 A18.E2 | A09.D2 194.61,123.98 193.66,124.93 82.53,124.93 81.58,123.98 A18.D2
  Bottom 0.127: A18.E2 83.49,120.8 81.27,123.02 A18.D2 | v88.25,119.85 88.89,119.21 88.89,106.52 87.61,105.24 A18.L1
0RD_P_H  (via drill 0.61)
  Top 0.127: v104.76,123.02 104.12,122.39 83.8,122.39 80.63,119.21 64.12,119.21 62.53,117.63 A20.F1
  Bottom 0.127: A20.F1 62.21,117.94 63.17,118.9 63.17,128.42 62.21,129.38 A20.B1 | 105.08,123.34 105.39,123.02 105.39,118.58 106.03,117.94 A16.F2 | 105.08,123.34 105.08,123.98 106.67,125.56 115.24,125.56 115.24,126.52 A16.C1 | v104.76,123.02 105.08,123.34
0RD_PARITY_L  (via drill 0.61)
  Top 0.127: v91.74,52.54 16.5,52.54 14.91,50.95 B24.E1
  Bottom 0.127: v91.74,52.54 111.43,72.22 111.43,76.99 110.79,77.62 110.79,103.02 110.16,103.66 110.16,106.83 110.79,107.47 110.79,116.67 109.2,118.26 109.2,119.85 A16.E2
0RD_REV_L  (via drill 0.61)
  Top 0.127: A18.S1 91.11,89.05 92.06,90 125.72,90 128.26,87.46 132.07,87.46 136.19,91.59 137.46,91.59 A14.R1 | v90.16,112.23 86.34,112.23 84.76,113.82 A18.H2
  Bottom 0.127: v90.16,112.23 91.74,110.64 91.74,90.32 90.79,89.37 A18.S1
0READ_WRITE_H  (via drill 0.61)
  Top 0.127: 130.8,121.75 v133.02,119.53 | 130.8,121.75 98.41,121.75 97.46,120.8 A17.E2 | 187.95,121.75 130.8,121.75 | 187.95,121.75 260.34,121.75 261.29,120.8 A04.E2 | A24.T2 5.38,85.88 6.33,86.83 180.96,86.83 181.91,85.88 A10.T2 | v187.95,120.17 187.95,121.75 | v187.95,101.75 186.36,101.75 A10.M2
  Bottom 0.127: v133.02,119.53 133.02,116.36 134.61,114.77 A14.H2 | A10.M2 185.41,100.8 183.82,99.21 183.82,87.15 182.87,86.19 A10.T2 | v187.95,120.17 187.63,119.85 187.63,113.82 190.17,111.28 190.17,107.47 187.63,104.93 187.63,102.07 v187.95,101.75
0RESET_L  (via drill 0.61)
  Top 0.127: v94.28,101.12 95.87,102.7 101.58,102.7 | 101.58,102.7 102.54,101.75 A17.M1 | 138.42,101.43 137.15,102.7 101.58,102.7 | 138.42,101.43 v139.37,100.48 | v207.95,99.85 181.28,99.85 180.01,101.12 A11.M1 178.74,101.75 177.79,102.7 139.69,102.7 138.42,101.43
  Bottom 0.127: v94.28,101.12 94.92,100.48 94.92,93.5 93.97,92.54 A17.R2 | v139.37,100.48 139.37,95.08 136.83,92.54 136.83,90.96 135.24,89.37 A14.S2 | A11.M1 179.69,102.07 180.64,103.02 180.64,110.01 180.01,110.64 180.01,113.18 180.64,113.82 180.64,115.72 179.69,116.67 179.69,119.85 A11.E1 | v207.95,99.85 209.22,98.58 209.22,87.15 208.27,86.19 A08.T2
0REV_ENABLE  (via drill 0.61)
  Top 0.127: v92.38,115.72 92.69,116.04 102.22,116.04 103.49,117.31 104.76,117.31 106.03,116.04 117.46,116.04 118.41,116.99 A15.F2
  Bottom 0.127: v92.38,115.72 92.38,99.85 93.33,98.89 A17.N2
0REWIND_L  (via drill 0.61)
  Top 0.127: v171.44,120.8 167.31,120.8 A12.E1 | v15.22,123.66 11.73,123.66 A24.D1
  Bottom 0.127: v171.44,120.8 171.75,121.12 171.75,127.15 177.47,132.87 | 177.47,132.87 178.74,132.87 A11.A1 | v15.22,123.66 39.04,147.47 177.47,147.47 177.47,132.87
0RWND_DONE_L
  Top 0.127: A12.S2 159.69,89.05 157.47,91.27 A12.R2
  Bottom 0.127: A12.T2 156.83,86.19 156.83,91.27 A12.R2 | A12.P2 160.01,94.45 160.01,89.37 A12.S2
0STROBE_H  (via drill 0.61)
  Top 0.127: v180.64,129.38 180.01,128.74 135.88,128.74 134.61,130.01 133.34,130.01 132.07,128.74 115.55,128.74 v114.92,129.38
  Bottom 0.127: v180.64,129.38 180.64,125.88 182.23,124.29 A10.D2 | v114.92,129.38 113.02,129.38 A16.B1
0STROBE_L  (via drill 0.61)
  Top 0.127: v136.51,45.87 16.18,45.87 14.91,44.6 B24.H1
  Bottom 0.127: A13.S1 153.66,88.1 153.66,83.02 A13.U1 153.97,81.75 153.97,63.34 v136.51,45.87 136.19,45.55 120.64,61.11 120.64,98.26 119.68,99.21 119.68,99.85 120.32,100.48 120.32,111.28 117.78,113.82 117.78,117.63 120.32,120.17 120.32,137.63 119.05,137.63 117.14,135.72 117.14,134.77 116.19,133.82 A16.A1
00SYNC_FWD_H
  Bottom 0.127: A15.B1 125.72,129.38 126.98,128.11 126.98,117.31 133.65,110.64 133.65,96.67 134.61,95.72 A14.P2
0SYNC_FWD_L  (via drill 0.61)
  Top 0.127: A24.P2 8.56,95.4 9.83,96.67 14.27,96.67 17.13,99.53 66.66,99.53 67.61,98.58 A19.N2 68.88,98.58 71.11,100.8 A19.M2 | v123.49,132.23 123.17,131.92 118.09,131.92 117.46,132.55 116.83,132.55 116.19,131.92 106.03,131.92 103.49,134.46 99.68,134.46 96.82,131.6 v80.95,131.6
  Bottom 0.127: A15.L1 125.08,105.24 125.08,109.69 124.13,110.64 124.13,112.55 126.67,115.09 126.67,122.07 125.72,123.02 A15.D1 125.08,124.29 123.49,125.88 v123.49,132.23 | v80.95,131.6 72.69,123.34 72.69,103.02 71.74,102.07 A19.M2
00SYNC_REV_H  (via drill 0.61)
  Top 0.127: v142.86,110.01 142.23,109.37 124.13,109.37 v123.49,110.01
  Bottom 0.127: v142.86,110.01 142.86,97.62 143.5,96.99 143.5,96.35 142.86,95.72 142.86,90.64 141.59,89.37 A14.S1 | v123.49,110.01 123.81,110.32 123.81,118.58 122.54,119.85 A15.E2
0SYNC_REV_L  (via drill 0.61)
  Top 0.127: v124.76,114.45 122.86,114.45 A15.H2 | A24.S2 8.56,89.05 10.14,90.64 27.29,90.64 30.46,93.81 69.83,93.81 70.79,94.77 A19.P2 | v123.49,76.99 122.86,77.62 v78.41,77.62
  Bottom 0.127: v124.76,114.45 125.08,114.77 125.08,116.67 A15.F1 | v123.49,76.99 123.49,97.94 120.95,100.48 120.95,112.55 121.91,113.5 A15.H2 | v78.41,77.62 72.69,83.34 72.69,93.5 71.74,94.45 A19.P2
0TM_L  (via drill 0.61)
  Top 0.127: v34.59,144.3 35.23,143.66 213.98,143.66 216.2,141.44 265.73,141.44 270.5,136.68 270.5,134.46 v266.69,134.46
  Bottom 0.127: v34.59,144.3 6.33,116.04 6.33,46.19 7.61,44.92 B24.H2 | v266.69,134.46 266.37,134.14 266.37,118.9 265.42,117.94 A04.F1
0TR_READY_H  (via drill 0.61)
  Top 0.127: v215.57,143.34 214.93,143.98 126.03,143.98 v125.4,144.62
  Bottom 0.127: v215.57,143.34 215.57,120.8 217.47,118.9 217.47,116.04 216.2,114.77 216.2,96.67 217.16,95.72 A08.P1 | v125.4,144.62 124.76,144.62 98.73,118.58 98.73,116.99 99.68,116.04 99.68,111.59 A17.J1
0TR_READY_L  (via drill 0.61)
  Top 0.127: B24.K2 8.56,38.25 10.14,39.84 14.59,39.84 18.72,43.97 19.35,43.97 20.3,43.02 153.97,43.02 v156.2,45.24 156.51,45.55 181.91,45.55 v182.23,45.24 | v227.63,135.41 261.29,135.41 263.19,133.5 267.64,133.5 A04.A1 | v221.6,96.99 221.6,97.62 221.92,97.94 221.92,99.53 215.89,99.53 214.93,98.58 A08.N1
  Bottom 0.127: v156.2,45.24 159.05,48.09 159.05,80.8 160.01,81.75 A12.U2 | v182.23,45.24 212.71,75.72 212.71,96.35 213.98,97.62 A08.N1 | v227.63,135.41 222.55,130.33 222.55,116.04 222.87,115.72 222.87,114.77 221.92,113.82 221.92,97.31 v221.6,96.99
0WDATA00L  (via drill 0.61)
  Top 0.127: v44.75,130.96 46.98,128.74 90.79,128.74 93.33,131.28 116.19,131.28 116.83,130.65 118.09,130.65 118.73,131.28 205.73,131.28 206.68,132.23 210.49,132.23 210.81,131.92 214.62,131.92 217.16,134.46 220.97,134.46 223.51,131.92 232.4,131.92 v232.71,132.23 | v232.71,108.1 230.81,108.1 A07.K1
  Bottom 0.127: v44.75,130.96 44.75,134.46 26.66,134.46 16.18,123.98 16.18,103.66 14.59,102.07 A24.M1 | v232.71,132.23 232.08,131.6 232.08,120.17 232.71,119.53 232.71,118.26 232.08,117.63 232.08,108.74 v232.71,108.1
0WDATA01L  (via drill 0.61)
  Top 0.127: v15.22,67.78 172.07,67.78 v172.71,67.14 | v184.14,78.57 184.77,77.94 201.92,77.94 202.87,78.89 202.87,80.8 v202.55,80.8 | v202.23,100.8 202.87,100.16 207,100.16 207.63,100.8 210.17,100.8 210.81,100.16 228.59,100.16 229.54,101.12 A07.M1
  Bottom 0.127: v15.22,67.78 12.68,70.32 12.68,93.18 13.96,94.45 A24.P1 | v184.14,78.57 v172.71,67.14 | v202.55,80.8 202.87,81.11 202.87,95.4 200.33,97.94 200.33,98.89 v202.23,100.8
0WDATA02L  (via drill 0.61)
  Top 0.127: v15.22,69.05 16.18,68.1 v201.28,68.1 | v207.63,74.45 208.27,75.08 219.06,75.08 v226.68,82.7 | v227.63,94.45 227.95,94.77 229.54,94.77 A07.P1
  Bottom 0.127: v15.22,69.05 13,71.27 13,87.15 13.96,88.1 A24.S1 | v201.28,68.1 v207.63,74.45 | v226.68,82.7 228.27,84.29 228.27,93.81 v227.63,94.45
0WDATA03L  (via drill 0.61)
  Top 0.127: v232.4,63.65 230.81,62.06 172.71,62.06 170.17,64.6 152.7,64.6 150.16,62.06 6.65,62.06 6.65,76.35 10.78,80.48 12.05,80.48 13.64,82.07 A24.U1
  Bottom 0.127: v232.4,63.65 232.4,71.27 230.81,72.86 230.81,81.43 231.44,82.07 231.44,85.56 230.17,86.83 230.17,88.1 A07.S1
0WDATA04L  (via drill 0.61)
  Top 0.127: v64.12,77.62 13,77.62 11.73,78.89 A24.V1 | v72.69,69.05 73.33,69.68 228.27,69.68 v229.54,70.95
  Bottom 0.127: v72.69,69.05 v64.12,77.62 | v229.54,70.95 230.49,71.91 230.49,81.75 A07.U1
0WDATA05L  (via drill 0.61)
  Top 0.127: v230.17,118.9 227,118.9 226.36,118.26 221.92,118.26 221.28,117.63 A07.F2 | v231.76,136.36 229.54,138.58 189.22,138.58 188.9,138.27 139.05,138.27 136.83,140.49 65.39,140.49 62.21,137.31 v15.54,137.31
  Bottom 0.127: v230.17,118.9 231.76,120.48 v231.76,136.36 | v15.54,137.31 5.07,126.83 5.07,124.29 A24.D2
0WDATA06L  (via drill 0.61)
  Top 0.127: v204.46,142.71 204.14,143.03 v22.53,143.03
  Bottom 0.127: v204.46,142.71 204.46,144.3 215.89,144.3 219.38,140.81 219.38,112.55 220.33,111.59 A07.J2 | v22.53,143.03 9.19,129.69 9.19,122.07 8.24,121.12 A24.E2
0WDATA07L  (via drill 0.61)
  Top 0.127: v215.57,70.95 214.62,70 v8.88,70
  Bottom 0.127: v215.57,70.95 215.57,88.42 219.7,92.54 219.7,96.35 219.38,96.67 219.38,98.58 220.65,99.85 220.65,103.97 A07.L2 | v8.88,70 9.19,70.32 9.19,112.55 8.24,113.5 A24.H2
0WR_LD_L  (via drill 0.61)
  Top 0.127: v157.47,126.2 159.69,128.42 195.25,128.42 v197.15,130.33
  Bottom 0.127: v157.47,126.2 155.88,124.61 155.88,112.55 156.83,111.59 A12.J2 | v197.15,130.33 199.69,127.79 199.69,122.07 198.74,121.12 A09.E2
0WR_SET_H  (via drill 0.61)
  Top 0.127: v98.73,126.52 100.31,128.11 136.51,128.11 v137.15,127.47
  Bottom 0.127: v98.73,126.52 98.09,125.88 98.09,115.72 97.14,114.77 A17.H2 | v137.15,127.47 140.96,123.66 140.96,121.12 A14.E1
1AC00L  (via drill 0.61)
  Top 0.127: v213.03,57.94 213.98,58.89 225.41,58.89 226.36,59.84 B07.B1
  Bottom 0.127: v213.03,57.94 213.03,49.05 213.98,48.09 B08.F1
1AC01L  (via drill 0.61)
  Top 0.127: v215.89,48.73 216.52,49.37 228.59,49.37 229.54,50.32 B07.E1
  Bottom 0.127: v215.89,48.73 215.89,43.02 214.62,41.74 B08.J1
1AC02L  (via drill 0.61)
  Top 0.127: v214.93,43.97 216.52,45.55 228.59,45.55 229.54,44.6 B07.H1
  Bottom 0.127: v214.93,43.97 213.03,42.06 213.03,36.35 213.98,35.4 B08.L1
1IOT04L
  Top 0.127: B11.R1 176.52,21.43 176.52,17.62 196.84,17.62 197.79,18.57 B09.S2
1IOT06_2L  (via drill 0.61)
  Top 0.127: v46.98,103.66 46.34,103.02 25.7,103.02 24.43,104.29 A23.L1 | v90.47,30 196.52,30 197.79,31.27 B09.M2
  Bottom 0.127: v46.98,103.66 47.29,103.34 47.29,92.54 41.58,86.83 41.58,78.89 v90.47,30
1MB09H
  Top 0.127: B18.S2 83.49,19.2 81.27,21.43 B18.R2 81.58,22.38 83.17,23.96 126.98,23.96 127.94,24.92 B15.P1 | B09.J2 194.61,41.43 177.47,41.43 176.52,42.38 120.64,42.38 119.68,41.43 B15.J2
  Bottom 0.127: B09.J2 195.57,41.74 197.15,43.33 197.15,47.46 210.17,60.48 211.44,60.48 211.44,58.89 209.85,57.3 209.85,56.67 210.81,55.72 212.39,55.72 212.39,57.3 212.08,57.62 212.08,58.26 213.66,59.84 B08.B1 | B15.P1 128.89,25.87 139.69,36.66 139.69,37.3 137.15,39.84 119.36,39.84 119.36,40.48 B15.J2
1MB09L  (via drill 0.61)
  Top 0.127: v138.73,36.98 139.05,36.66 203.19,36.66 204.14,37.62 B09.K1 205.41,37.62 206.68,37.62 210.81,33.49 220.33,33.49 220.33,29.05 B07.N2 | v215.57,52.86 214.62,51.91 206.36,51.91 205.41,50.95 B09.E1
  Bottom 0.127: v138.73,36.98 124.13,22.38 124.13,16.03 119.68,16.03 B15.T2 | B09.E1 204.46,50 203.5,49.05 203.5,39.52 204.46,38.57 B09.K1 | v215.57,52.86 215.57,61.11 217.16,62.7 B08.A1
1MB10H
  Top 0.127: B15.K2 122.86,37.62 124.44,36.03 200.01,36.03 200.96,35.08 B09.L1
  Bottom 0.127: B08.D2 207.63,53.18 206.36,51.91 206.36,31.59 205.09,30.32 201.92,30.32 201.92,34.12 B09.L1
1MB10L  (via drill 0.61)
  Top 0.127: B18.T2 81.58,15.39 83.17,13.81 86.98,13.81 89.52,11.27 120.64,11.27 121.59,12.22 B15.U2 122.86,12.22 123.81,11.27 v181.91,11.27 | v220.01,26.51 197.47,26.51 195.88,28.09 B09.N2 | v221.6,55.72 219.06,55.72 218.11,56.67 B08.C1
  Bottom 0.127: B07.R2 220.33,22.7 220.33,26.19 v220.01,26.51 220.33,26.51 222.24,28.41 222.24,55.08 v221.6,55.72 | v181.91,11.27 194.93,24.28 194.93,27.78 B09.N2
1MB11H
  Bottom 0.127: B15.R1 125.72,21.43 127.3,19.84 127.3,18.57 137.78,8.09 216.2,8.09 216.2,47.78 217.16,48.73 217.16,50 B08.E1
1MB11L
  Top 0.127: B08.D1 213.66,53.49 212.39,52.22 204.77,52.22 201.92,49.37 201.92,48.09 B09.F1
  Bottom 0.127: B09.P2 198.11,25.87 197.15,26.82 197.15,36.35 198.11,37.3 B09.K2 198.74,38.57 198.74,39.84 201.6,42.7 201.6,46.83 B09.F1 | B07.T2 220.33,16.35 218.74,17.93 218.74,50.95 217.79,51.91 214.62,51.91 214.62,53.18 B08.D1
1MYOP1  (via drill 0.61)
  Top 0.127: B18.U2 84.76,12.22 86.34,10.63 117.46,10.63 118.41,9.68 B15.V2 | B09.M1 204.14,31.9 202.55,33.49 120.64,33.49 119.68,34.44 B15.L2 | v210.49,59.52 212.39,61.43 240.65,61.43 242.24,63.02 B06.A1
  Bottom 0.127: B15.V2 118.73,10 117.78,10.95 117.78,33.17 118.73,34.12 B15.L2 | v210.49,59.52 206.04,55.08 206.04,33.17 205.09,32.22 B09.M1
1MYOP2  (via drill 0.61)
  Top 0.127: v200.65,43.33 203.5,43.33 204.14,43.97 B09.H1 205.41,43.97 206.36,43.02 238.43,43.02 v242.24,46.83
  Bottom 0.127: B15.S1 129.21,19.2 171.75,19.2 176.52,23.96 193.98,23.96 193.98,33.17 194.93,34.12 B09.L2 195.57,35.4 195.57,38.25 v200.65,43.33 | v242.24,46.83 241.6,47.46 241.6,55.4 242.56,56.35 B06.C1
1MYOP4  (via drill 0.61)
  Top 0.127: v209.54,44.29 211.12,45.87 230.17,45.87 233.35,49.05 240.97,49.05 242.24,50.32 B06.E1
  Bottom 0.127: v209.54,44.29 209.54,34.12 200.33,24.92 200.33,22.38 195.88,22.38 B09.R2
1R_RESET_L  (via drill 0.61)
  Top 0.127: v177.79,42.38 229.86,42.38 235.57,36.66 241.29,36.66 242.24,37.62 B06.K1 | v22.21,60.16 23.48,58.89 174.61,58.89 175.56,59.84 B11.B1
  Bottom 0.127: 177.47,42.38 177.47,58.57 176.52,59.52 B11.B1 | 177.47,42.38 177.47,27.46 179.06,25.87 B11.P1 | v177.79,42.38 177.47,42.38 | v22.21,60.16 22.21,105.88 20.94,107.15 A23.K2
1WDATA00L  (via drill 0.61)
  Top 0.127: v97.46,42.06 99.68,39.84 227.95,39.84 229.54,38.25 B07.K1 | v60.63,100.48 60.63,102.7 28.56,102.7 27.61,101.75 A23.M1
  Bottom 0.127: v97.46,42.06 60.63,78.89 v60.63,100.48
1WDATA01L  (via drill 0.61)
  Top 0.127: v231.44,70.32 229.86,71.91 133.34,71.91 132.7,71.27 32.69,71.27 v27.29,76.67
  Bottom 0.127: v231.44,70.32 231.44,33.17 230.49,32.22 B07.M1 | v27.29,76.67 25.7,78.26 25.7,93.5 26.66,94.45 A23.P1
1WDATA02L  (via drill 0.61)
  Top 0.127: v104.12,29.05 106.03,27.14 168.9,27.14 172.07,23.96 224.14,23.96 224.46,24.28 228.9,24.28 229.54,24.92 B07.P1 | v50.47,87.78 50.15,87.46 28.56,87.46 27.61,88.42 A23.S1
  Bottom 0.127: v104.12,29.05 50.47,82.7 v50.47,87.78
1WDATA03L  (via drill 0.61)
  Top 0.127: v35.23,31.9 40.31,26.82 168.58,26.82 172.07,23.33 222.87,23.33 227,19.2 229.54,19.2 B07.S1
  Bottom 0.127: v35.23,31.9 28.24,38.89 28.24,80.8 27.29,81.75 A23.U1
1WDATA04L  (via drill 0.61)
  Top 0.127: v33.96,25.55 42.53,16.98 84.44,16.98 87.61,13.81 228.59,13.81 229.54,12.85 B07.U1
  Bottom 0.127: v33.96,25.55 33.96,26.19 22.53,37.62 22.53,47.78 25.07,50.32 25.07,77.62 24.11,78.57 A23.V1
1WDATA05L  (via drill 0.61)
  Top 0.127: v18.08,49.37 128.89,49.37 131.11,51.59 132.7,51.59 138.1,46.19 219.06,46.19 220.01,47.14 B07.F2
  Bottom 0.127: v18.08,49.37 18.72,50 18.72,122.07 17.77,123.02 A23.D2
1WDATA06L  (via drill 0.61)
  Top 0.127: v220.01,38.89 219.38,39.52 37.77,39.52 v35.23,42.06
  Bottom 0.127: v220.01,38.89 220.01,40.16 220.33,40.48 B07.J2 | v35.23,42.06 28.56,48.73 28.56,104.61 21.89,111.28 21.89,118.9 20.94,119.85 A23.E2
1WDATA07L  (via drill 0.61)
  Top 0.127: v19.35,42.7 22.84,39.2 214.62,39.2 218.74,35.08 220.01,35.08 B07.L2
  Bottom 0.127: v19.35,42.7 19.35,112.55 20.3,113.5 A23.H2
A06V1  (via drill 0.61)
  Top 0.127: A06.U2 236.84,81.75 239.06,79.53 A06.V1 | v238.11,104.29 233.98,104.29 A06.L2
  Bottom 0.127: A06.N2 233.03,98.89 233.03,103.97 A06.L2 | 238.43,104.29 238.43,80.8 239.38,79.84 A06.V1 | 238.43,104.29 238.43,109.37 239.38,110.32 A06.J1 | 238.43,104.29 v238.11,104.29
A11U1  (via drill 0.61)
  Top 0.127: v186.99,132.23 190.8,132.23 191.44,132.87 A10.A1
  Bottom 0.127: A11.U1 179.69,83.02 181.28,84.61 181.28,99.53 185.41,103.66 185.41,107.15 A10.K2 186.04,108.42 186.99,109.37 v186.99,132.23
A13R1  (via drill 0.61)
  Top 0.127: v152.07,110.01 151.75,109.69 146.04,109.69 145.08,110.64 A13.J2
  Bottom 0.127: A13.R1 151.12,92.54 152.39,93.81 152.39,99.53 153.66,100.8 A13.M1 153.66,102.07 152.7,103.02 152.7,109.37 v152.07,110.01
AC00L  (via drill 0.61)
  Top 0.127: v264.46,108.42 262.56,106.52 257.16,106.52 256.21,107.47 A05.K1 | v278.75,124.93 266.69,124.93 265.73,123.98 A04.D1
  Bottom 0.127: v264.46,108.42 264.46,110.01 263.83,110.64 263.83,122.07 264.78,123.02 A04.D1 | 279.07,124.93 279.07,128.42 278.12,129.38 A03.B1 | 279.07,124.93 279.07,61.75 278.12,60.8 B03.B1 | 279.07,124.93 v278.75,124.93
AC01L
  Top 0.127: A04.E1 268.91,120.8 270.5,122.39 276.21,122.39 277.16,123.34 A03.D1
  Bottom 0.127: B03.D1 278.12,54.45 279.38,55.72 279.38,124.29 279.7,124.61 279.7,125.88 279.38,126.2 279.38,130.01 278.12,131.28 276.53,131.28 276.53,125.25 277.48,124.29 A03.D1
AC02L  (via drill 0.61)
  Top 0.127: v283.83,50.95 281.61,50.95 B03.E1 | v286.37,109.05 269.86,109.05 268.91,108.1 A04.K1
  Bottom 0.127: v283.83,50.95 285.74,52.86 285.74,109.05 | 285.74,109.05 285.74,123.66 284.47,124.93 281.29,124.93 281.29,121.12 A03.E1 | 285.74,109.05 v286.37,109.05
AC03L  (via drill 0.61)
  Top 0.127: v280.34,103.34 266.69,103.34 265.73,104.29 A04.L1
  Bottom 0.127: 279.7,103.97 v280.34,103.34 | 279.7,103.97 279.7,112.55 280.66,113.5 A03.H1 | 279.7,103.97 279.7,45.87 280.66,44.92 B03.H1
AC04L  (via drill 0.61)
  Top 0.127: v264.46,43.02 275.57,43.02 277.16,41.43 B03.J1 | A05.R1 253.03,92.23 253.99,93.18 263.51,93.18 264.46,92.23 A04.R1 | v265.42,107.15 267.64,109.37 275.89,109.37 277.16,110.64 A03.J1
  Bottom 0.127: v264.46,43.02 263.83,43.65 263.83,90.32 | 263.83,90.32 264.78,91.27 A04.R1 | v265.42,107.15 263.83,105.56 263.83,90.32
AC05L  (via drill 0.61)
  Top 0.127: A05.S1 256.21,89.05 257.16,90 266.69,90 267.64,89.05 A04.S1 268.91,89.05 269.86,90 v276.85,90
  Bottom 0.127: 276.53,90 276.53,103.02 277.48,103.97 A03.L1 | 276.53,90 276.53,36.35 277.48,35.4 B03.L1 | 276.53,90 v276.85,90
AC06L  (via drill 0.61)
  Top 0.127: A05.H2 249.86,114.45 250.81,115.4 260.34,115.4 261.29,114.45 A04.H2 | v262.56,104.93 264.78,102.7 279.38,102.7 280.34,101.75 A03.M1
  Bottom 0.127: B03.M1 280.66,30.95 279.7,30 279.7,24.92 280.66,23.96 282.56,23.96 282.56,99.53 281.29,100.8 A03.M1 | v262.56,104.93 263.19,105.56 263.19,108.1 262.56,108.74 262.56,113.18 262.24,113.5 A04.H2
AC07L  (via drill 0.61)
  Top 0.127: A05.J2 246.68,110.64 247.64,109.69 257.16,109.69 258.11,110.64 A04.J2 | v260.65,97.31 261.61,96.35 279.38,96.35 280.34,95.4 A03.P1
  Bottom 0.127: B03.P1 281.29,25.87 282.24,26.82 282.24,93.5 281.29,94.45 A03.P1 | v260.65,97.31 260.65,104.29 259.06,105.88 259.06,110.32 A04.J2
AC08L  (via drill 0.61)
  Top 0.127: A05.N2 246.68,98.58 247.64,99.53 257.16,99.53 258.11,98.58 A04.N2 | v295.9,86.83 295.26,87.46 282.56,87.46 | 282.56,87.46 281.61,88.42 A03.S1 | v259.38,89.05 260.97,87.46 282.56,87.46
  Bottom 0.127: v295.9,86.83 295.26,86.19 295.26,8.09 283.83,8.09 282.56,9.36 282.56,16.98 281.29,18.25 B03.S1 | v259.38,89.05 260.02,89.69 260.02,96.67 259.06,97.62 A04.N2
AC09L  (via drill 0.61)
  Top 0.127: v255.57,54.13 270.81,54.13 B03.D2
  Bottom 0.127: v255.57,54.13 250.49,59.21 250.49,93.5 249.54,94.45 A05.P2 | A03.D2 271.76,123.02 272.72,122.07 272.72,58.26 271.45,56.98 271.45,54.45 B03.D2
AC10L  (via drill 0.61)
  Top 0.127: v255.57,50.95 256.21,51.59 273.35,51.59 273.99,50.95 B03.E2 | v292.72,79.53 290.81,77.62 250.81,77.62 249.54,78.89 249.54,81.75 A05.U2
  Bottom 0.127: v255.57,50.95 249.54,56.98 249.54,81.75 A05.U2 | v292.72,79.53 292.09,80.16 292.09,134.46 278.43,134.46 275.89,131.92 275.89,122.07 274.94,121.12 A03.E2
AC11L  (via drill 0.61)
  Top 0.127: v249.22,47.14 251.76,44.6 273.99,44.6 B03.H2
  Bottom 0.127: v249.22,47.14 249.22,75.72 246.37,78.57 A05.V2 | A03.H2 274.94,113.5 275.89,112.55 275.89,45.87 274.94,44.92 B03.H2
B06V1
  Top 0.127: B06.U2 236.84,11.9 239.06,9.68 B06.V1
  Bottom 0.127: B06.L2 233.03,34.12 233.03,29.05 B06.N2 233.67,27.78 233.98,27.46 233.98,24.92 238.11,20.79 | 238.11,20.79 238.11,14.44 236.84,13.17 B06.U2 | 238.11,20.79 238.11,34.76 238.75,35.4 238.75,39.84 239.38,40.48 B06.J1
BAC00
  Top 0.127: A01.B1 302.56,130.33 301.29,131.6 234.62,131.6 233.03,133.19 230.81,133.19 A07.A1
  Bottom 0.127: B01.B1 302.88,60.8 301.93,61.75 301.93,128.42 302.88,129.38 A01.B1 | B07.A1 229.86,63.97 228.59,65.24 228.59,102.07 228.9,102.39 228.9,131.6 229.86,132.55 A07.A1
BAC01  (via drill 0.61)
  Top 0.127: B07.D1 227.63,53.49 228.9,52.22 301.29,52.22 302.56,53.49 B01.D1 | A07.D1 227.63,123.98 228.9,125.25 277.8,125.25 278.43,125.88 280.34,125.88 281.29,124.93 301.61,124.93 302.56,123.98 A01.D1 | v227.32,77.3 v229.54,79.53 | v229.54,96.67 v227.63,96.67
  Bottom 0.127: v227.32,77.3 227.32,67.78 225.73,66.19 225.73,55.4 226.68,54.45 B07.D1 | v229.54,79.53 228.9,80.16 228.9,96.04 v229.54,96.67 | v227.63,96.67 228.27,97.31 228.27,101.12 227,102.39 227,103.02 228.27,104.29 228.27,122.07 227.32,123.02 A07.D1
BAC02  (via drill 0.61)
  Top 0.127: v304.15,48.73 305.74,50.32 B01.E1 | v260.65,117.63 259.06,116.04 228.59,116.04 227.63,116.99 A07.F1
